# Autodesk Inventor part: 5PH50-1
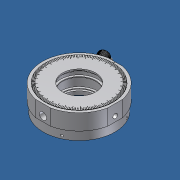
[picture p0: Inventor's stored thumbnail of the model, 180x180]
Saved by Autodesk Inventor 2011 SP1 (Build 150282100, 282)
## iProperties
Created: 2011-06
Part Number: 5PH50-1
Document SubType Name: Modeling
Designer: Darius
Density: 1 g/cm^3
Author: Darius
Translation Standard: STEP AP203
FileName: 5PH50-1.STEP
PreProcessor: SolidWorks 2003240
PostProcessor: Build: 282, Release: 2011 SP1 - Date: Thu 08/05/2010
Sent Units: millimeter
Uncertainty: 1e-05
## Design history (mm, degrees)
feature "Base1"
node "NONE"
